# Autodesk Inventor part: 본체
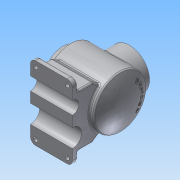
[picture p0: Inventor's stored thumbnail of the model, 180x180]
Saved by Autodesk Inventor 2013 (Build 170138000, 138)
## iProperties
Created: 2018-08
Part Number: 본체
Material: 알루미늄 6061
Document SubType Name: Modeling
Designer: Administrator
Density: 2.71 g/cm^3
Mass: 1886 g
Surface Area: 1087.46 cm^2
Volume: 695.94 cm^3
Author: Administrator
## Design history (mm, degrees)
sketch "스케치2"
  geometry: L1 (0, 38)-(12, 38); L2 (12, 38)-(12, 50); L3 (12, 50)-(108.671, 50); L4 (0, 38)-(0, 0); L5 (0, 0)-(120, 0); A1 r 116 centre (4, 0) between (120, 0) and (108.671, 50)
  constraints: 10 end point, 3 perpendicular, 2 point on circle, 1 centre point, 1 horizontal, 1 parallel, 1 point on line
  dimensions: "d24" = 120 distance of L4.end L5.end; "d26" = 76 diameter of L1 L5; "d27" = 12 distance of L1.start L1.end; "d28" = 100 diameter of L3 L5; "d29" = 116 radius of A1
revolve "회전1" sketch "스케치2" stored, may be unused: angle "d30" = 90 deg
sketch "스케치3"
  geometry: L1 (12, 50)-(108.671, 50) reference; L2 (0, -38)-(0, 38) reference; L3 (22, 40)-(102.163, 40); L4 (0, 0)-(110, 0); L5 (22, 40)-(22, 27); L6 (22, 27)-(0, 27); L7 (0, 27)-(0, 0); A1 r 116 centre (4, 0) between (108.671, -50) and (108.671, 50) reference; A2 r 106 centre (4, 0) between (110, 0) and (102.163, 40)
  constraints: 10 end point, 3 perpendicular, 2 point on circle, 1 centre point, 1 horizontal, 1 parallel, 1 point on line
  dimensions: "d31" = 10 radial gap between concentric circles of A1 A2; "d32" = 80 diameter of L3 L4; "d33" = 22 distance of L5.end L6.end; "d34" = 54 diameter of L6 L4
revolve "회전2" sketch "스케치3" stored, may be unused: angle "d35" = 90 deg
node "작업 평면1"
sketch "스케치4"
  geometry: L1 (-20, -70)-(-100, -70); L2 (-100, -70)-(-100, 70); L3 (-100, 70)-(-20, 70); L4 (-20, 70)-(-20, -70); L5 (0, 38)-(0, -38) reference; L6 (-12, 50)-(-12, -50) reference; L7 (-12, -50)-(-108.671, -50) reference; L8 (-12, 50)-(-108.671, 50) reference; 3 further points
  constraints: 8 end point, 2 midpoint, 2 parallel, 1 horizontal, 1 horizontal alignment, 1 perpendicular
  dimensions: "d37" = 140 distance of L1.end L2.end; "d39" = 80 distance of L1.start L1.end; "d40" = 8 distance between parallel lines of L4 L6
extrude "돌출1" join sketch "스케치4" distance "d41" = 10; taper "d42" = 0 deg
node "작업 평면2"
sketch "스케치6"
  geometry: L1 (-72, -70)-(-82, -70) reference; L2 (-82, -70)-(-82, 70) reference; L3 (-82, 70)-(-72, 70) reference; L4 (-72, 70)-(-72, -70) reference; L5 (-43.437, 50)-(-72, 50); L6 (-72, 70)-(-43.437, 50); L7 (-43.437, 50)-(-29.59, 40.304); L8 (0, 0)-(-72, 0); L9 (-43.437, -50)-(-29.59, -40.304); L10 (-43.437, -50)-(-72, -50); L11 (-72, 50)-(-72, -50); C1 r 27 at (0, 0) reference; A1 r 50 centre (0, 0) between (-29.59, 40.304) and (-29.59, -40.304); 1 further point
  constraints: 14 end point, 3 symmetric about line, 2 point on circle, 1 centre point, 1 coincident, 1 collinear, 1 midpoint, 1 perpendicular, 1 point on line, 2 other
  dimensions: "d54" = 20 distance between parallel lines of L5 L3; "d56" = 35 deg angle of L3 L6; "d57" = 35 deg angle of L7 L3
extrude "돌출2" join sketch "스케치6" distance "d58" = 80; taper "d59" = 0 deg
sketch "스케치7"
  geometry: L1 (-28, 0)-(168, 0) reference; C1 r 12.5 at (42.5, 0); C2 r 17.5 at (92.5, 0); 1 further point
  constraints: 2 centre point, 2 point on line
  dimensions: "d60" = 25 diameter of C1; "d62" = 27.5 horizontal distance of C1.centre point (70, 82); "d63" = 35 diameter of C2; "d64" = 22.5 horizontal distance of point (70, 82) C2.centre
extrude "돌출3" cut sketch "스케치7" stored distance "d65" = 80; taper "d66" = 0 deg
node "작업 평면3"
sketch "스케치8"
  geometry: L1 (0, 38)-(0, -38) reference; C1 r 38 at (-62, 0); 2 further points
  constraints: 1 centre point, 1 horizontal alignment, 1 midpoint
  dimensions: "d68" = 76 diameter of C1; "d70" = 62 distance from line of C1.centre L1
extrude "돌출4" join sketch "스케치8" stored distance "d71" = 80; taper "d72" = 0 deg
hole "구멍1" diameter "d75" = 54; stored, may be unused: countersink angle "d79" = 90 deg, drill point angle "d81" = 118 deg; dims "d73" = 10, "d74" = 10, "d76" = 6, "d77" = 4, "d78" = 2, "d80" = 8
sketch "스케치9"
  geometry: L1 (15, -82)-(-5, -82) reference; 2 further points
  dimensions: "d83" = 32.5 distance of point (32.5, 0) point (0, 0); "d84" = 82 distance from line of L1 point (32.5, 0)
hole "구멍2" sketch "스케치9" at (32.5, 0) diameter "d85" = 3.242; stored, may be unused: countersink angle "d89" = 90 deg, drill point angle "d91" = 118 deg; dims "d86" = 8, "d87" = 4, "d88" = 2, "d90" = 10
sketch "스케치10"
  geometry: C1 r 27 at (0, 0) reference; 2 further points
  constraints: 1 vertical alignment
  dimensions: "d95" = 32.5 distance of C1.centre point (0, 32.5)
hole "구멍3" sketch "스케치10" at (0, 32.5) diameter "d96" = 3.242; stored, may be unused: countersink angle "d100" = 90 deg, drill point angle "d102" = 118 deg; dims "d97" = 8, "d98" = 4, "d99" = 2, "d101" = 10
node "작업 평면4"
sketch "스케치11"
  geometry: C1 r 32.5 at (0, 0); 1 further point
  constraints: 1 centre point, 1 coincident, 1 other
  dimensions: "d107" = 65 diameter of C1
feature "엠보싱1" sketch "스케치11" dims "d24" = 120, "d26" = 76, "d27" = 12, "d28" = 100, "d29" = 116, "d108" = 0.5, "d109" = 0
fillet "모깎기1" dims "d110" = 10
hole "구멍4" diameter "d113" = 8; stored, may be unused: countersink angle "d117" = 90 deg, drill point angle "d119" = 118 deg; dims "d114" = 10, "d115" = 4, "d116" = 2, "d118" = 10, "d120" = 10, "d121" = 10
hole "구멍5" diameter "d124" = 8; stored, may be unused: countersink angle "d128" = 90 deg, drill point angle "d130" = 118 deg; dims "d125" = 10, "d126" = 4, "d127" = 2, "d129" = 10, "d151" = 10, "d152" = 10
hole "구멍6" diameter "d133" = 8; stored, may be unused: countersink angle "d137" = 90 deg, drill point angle "d139" = 118 deg; dims "d134" = 10, "d135" = 4, "d136" = 2, "d138" = 10, "d149" = 10, "d150" = 10
hole "구멍7" diameter "d142" = 8; stored, may be unused: countersink angle "d146" = 90 deg, drill point angle "d148" = 118 deg; dims "d140" = 10, "d141" = 10, "d143" = 10, "d144" = 4, "d145" = 2, "d147" = 10
fillet "모깎기4" dims "d155" = 3
chamfer "모따기1" distance "d156" = 1; stored, may be unused: second distance "d157" = 2, angle "d158" = 45 deg
fillet "모깎기5" dims "d159" = 3
fillet "모깎기6" dims "d160" = 3
chamfer "모따기2" distance "d161" = 1; stored, may be unused: second distance "d162" = 2, angle "d163" = 45 deg
fillet "모깎기7" dims "d164" = 3
fillet "모깎기8" dims "d165" = 3
fillet "모깎기9" dims "d166" = 3
node "솔리드1"
pattern_circular "원형 패턴1" dims angle "d93" = 360 deg
pattern_circular "원형 패턴2" dims angle "d104" = 360 deg
node "절단 모서리 투영1"
other parameters: "d36" = -82, "d67" = 65, "d106" = 132.5
